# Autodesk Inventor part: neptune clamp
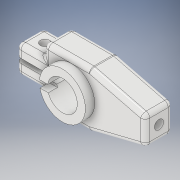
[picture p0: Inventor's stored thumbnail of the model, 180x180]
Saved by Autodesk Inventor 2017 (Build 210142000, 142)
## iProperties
Created: 2016-05
Part Number: neptune clamp
Material: Generic
Document SubType Name: Modeling
Designer: Stan
Density: 1 g/cm^3
Appearance: White
Author: Stan
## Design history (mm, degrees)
sketch "Sketch1"
  geometry: L1 (-9.525, 9.525)-(6.35, 9.525); L2 (6.35, -9.463)-(-9.525, -9.463); L3 (25.4, 4.763)-(25.4, -4.763); L4 (25.4, -4.763)-(6.35, -9.463); L5 (25.4, 4.763)-(6.35, 9.525); L6 (-9.525, 9.525)-(-9.525, 4.763); L7 (-9.525, 4.763)-(-19.05, 4.762); L8 (-19.05, -4.7)-(-9.525, -4.7); L9 (-9.525, -4.7)-(-9.525, -9.463); L10 (-5.103, 0.762)-(-19.05, 0.762); L11 (-5.103, -0.762)-(-19.05, -0.762); L12 (-19.05, -4.7)-(-19.05, -0.762); L13 (-19.05, 0.762)-(-19.05, 4.762); A1 r 5.159 centre (0, 0) between (-5.103, -0.762) and (-5.103, 0.762); 1 further point
  constraints: 26 end point, 4 perpendicular, 2 point on circle, 2 point on line, 2 vertical, 1 centre point, 1 coincident, 1 horizontal, 1 parallel
  dimensions: "d1" = 9.525 distance from line of L1 point (0, 0); "d2" = 25.4 horizontal distance of L3.end point (0, 0); "d4" = 9.525 distance of L3.start L3.end; "d5" = 4.7625 vertical distance of point (0, 0) L3.start; "d7" = 10.31875 diameter of A1; "d8" = 19.05 horizontal distance of L8.start point (0, 0); "d11" = 9.525 distance from line of point (0, 0) L6; "d12" = 19.05 distance from line of point (0, 0) L13; "d14" = 1.524 distance between parallel lines of L11 L10; "d15" = 0.762 distance from line of L10 point (0, 0); "d16" = 15.875 distance of L1.start L1.end; "d17" = 15.875 distance of L2.start L2.end; "d18" = 4.7625 distance between parallel lines of L2 L8; "d19" = 4.7625 distance between parallel lines of L7 L1
extrude "Extrusion1" new body sketch "Sketch1" distance "d20" = 9.525; taper "d21" = 0 deg
fillet "Fillet1" dims "d22" = 1.5875
sketch "Sketch2"
  geometry: C1 r 1.587 at (3.175, 3.519); 1 further point
  constraints: 1 centre point
  dimensions: "d23" = 3.175 diameter of C1
extrude "Extrusion2" cut sketch "Sketch2" distance "d24" = 15.875; taper "d25" = 0 deg
sketch "Sketch3"
  geometry: L1 (-1.587, 6.35)-(-1.588, 0) reference; C1 r 1.587 at (3.492, 3.175); 1 further point
  constraints: 1 centre point
  dimensions: "d26" = 3.175 diameter of C1; "d27" = 5.08 distance from line of C1.centre L1
extrude "Extrusion3" cut sketch "Sketch3" distance "d28" = 9.525; taper "d29" = 0 deg
fillet "Fillet2" dims "d30" = 1.5875
fillet "Fillet3" dims "d31" = 1.5875
sketch "Sketch4"
  geometry: L1 (-5.103, 0.762)-(-7.901, 0.762); L2 (-17.462, 0.762)-(-5.103, 0.762) reference; L3 (-4.888, -1.651)-(-7.764, -1.651); A1 r 7.938 centre (0, 0) between (-7.764, -1.651) and (-7.901, 0.762); A2 r 5.159 centre (0, 0) between (-4.888, -1.651) and (-5.103, 0.762); 1 further point
  constraints: 5 end point, 4 point on circle, 2 centre point, 2 coincident, 1 parallel, 1 point on line
  dimensions: "d32" = 15.875 diameter of A1
extrude "Extrusion4" join sketch "Sketch4" distance "d33" = 3.175; taper "d34" = 0 deg
body "Solid1"
